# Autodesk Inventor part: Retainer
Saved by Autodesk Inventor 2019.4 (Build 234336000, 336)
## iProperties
Created: 2021-08
Part Number: Retainer
Material: Generic
Document SubType Name: Modeling
Designer: Administrator
Density: 1 g/cm^3
Appearance: Default
Title: Retainer v8
Author: Administrator
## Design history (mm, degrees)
feature "Body1"
body "Solid1"
